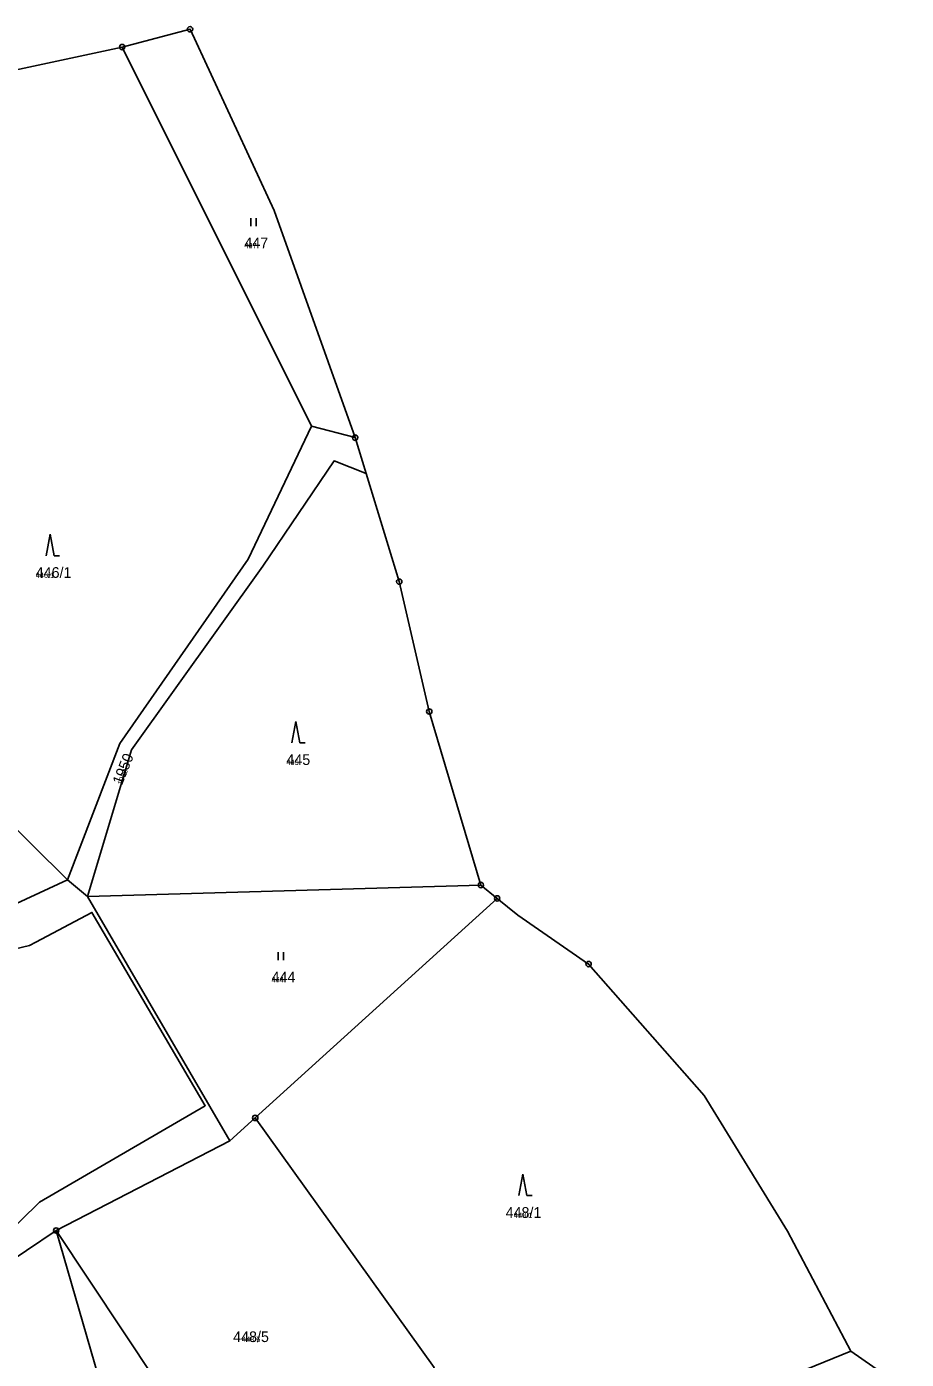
# Model space of a CAD drawing. Extents: x -763628 to -761565, y -976033 to -973833.
# Drawn here: x -761990.9 to -761826.2, y -974104.4 to -973855 of the extents above; entities that cross this region are included whole.
import ezdxf

# ---------------------------------------------------------------- set-up
doc = ezdxf.new("R2010")
doc.units = 0
for name, color, linetype in [('KN_cisla parcel 1000', 7, 'Continuous'), ('KN_cisla parcel 500', 7, 'Continuous'), ('KN_hranice parcel', 7, 'Continuous'), ('KN_hranice uzemi', 7, 'Continuous'), ('KN_znacky bodu BP', 7, 'Continuous'), ('KN_znacky kultur', 7, 'Continuous')]:
    doc.layers.add(name, color=color, linetype=linetype)

msp = doc.modelspace()

# ---------------------------------------------------------------- linework, layer by layer
at = {"layer": 'KN_hranice parcel'}
for p, q in [((-761937.58, -973929.76), (-761973.02, -973858.79)), ((-761937.58, -973929.76), (-761929.38, -973931.9)), ((-762035.47, -973963.03), (-761983.28, -974014.67)), ((-761983.28, -974014.67), (-761979.5, -974017.78)), ((-761905.85, -974015.63), (-761979.5, -974017.78)), ((-761979.5, -974017.78), (-761952.85, -974063.53)), ((-761948.1, -974059.22), (-761902.78, -974018.14)), ((-761952.85, -974063.53), (-761948.1, -974059.22)), ((-761952.85, -974063.53), (-761985.38, -974080.3)), ((-761985.38, -974080.3), (-762024.43, -974106.58)), ((-761976.43, -974111.24), (-761985.38, -974080.3))]:
    msp.add_line(p, q, dxfattribs=at)
for points in [[(-761983.28, -974014.67), (-761973.48, -973989.16), (-761949.45, -973954.64), (-761937.58, -973929.76)], [(-761927.32, -973938.61), (-761933.33, -973936.24), (-761946.68, -973955.95), (-761971.27, -973990.36), (-761979.5, -974017.78)], [(-762034.27, -973972.28), (-762024.59, -973979.11), (-762012.31, -974008.48), (-761996.38, -974020.73), (-761983.28, -974014.67)], [(-761994.56, -974027.98), (-761990.4, -974026.94), (-761989.2, -974026.35), (-761978.68, -974020.75), (-761957.46, -974056.95), (-761988.52, -974075.02), (-762005.87, -974091.94), (-762050.61, -974110.48), (-762074.41, -974109.33)], [(-761948.1, -974059.22), (-761914.58, -974105.93), (-761947.93, -974136.66), (-761985.38, -974080.3)], [(-761836.56, -974102.9), (-761855.09, -974110.42), (-761894.27, -974126.31)]]:
    msp.add_lwpolyline(points, dxfattribs=at)
at = {"layer": 'KN_hranice uzemi'}
for p, q in [((-761973.02, -973858.79), (-761960.31, -973855.47)), ((-761993.14, -973863.12), (-761973.02, -973858.79)), ((-761929.38, -973931.9), (-761927.32, -973938.61)), ((-761915.5, -973983.16), (-761905.85, -974015.63)), ((-761905.85, -974015.63), (-761902.78, -974018.14)), ((-761836.56, -974102.9), (-761826.15, -974110.09))]:
    msp.add_line(p, q, dxfattribs=at)
for points in [[(-761960.31, -973855.47), (-761944.58, -973889.38), (-761929.38, -973931.9)], [(-761927.32, -973938.61), (-761921.12, -973958.85), (-761915.5, -973983.16)], [(-761902.78, -974018.14), (-761898.91, -974021.3), (-761885.67, -974030.43)], [(-761885.67, -974030.43), (-761863.99, -974055.01), (-761848.4, -974080.42), (-761836.56, -974102.9)]]:
    msp.add_lwpolyline(points, dxfattribs=at)
at = {"layer": 'KN_znacky bodu BP'}
for centre, radius in [((-761960.31, -973855.47), 0.5), ((-761960.31, -973855.47), 0.0303), ((-761973.02, -973858.79), 0.5), ((-761973.02, -973858.79), 0.0303), ((-761929.38, -973931.9), 0.5), ((-761929.38, -973931.9), 0.0303), ((-761921.12, -973958.85), 0.5), ((-761921.12, -973958.85), 0.0303), ((-761915.5, -973983.16), 0.5), ((-761915.5, -973983.16), 0.0303), ((-761905.85, -974015.63), 0.5), ((-761905.85, -974015.63), 0.0303), ((-761902.78, -974018.14), 0.5), ((-761902.78, -974018.14), 0.0303), ((-761885.67, -974030.43), 0.5), ((-761885.67, -974030.43), 0.0303), ((-761948.1, -974059.22), 0.5), ((-761948.1, -974059.22), 0.0303), ((-761985.38, -974080.3), 0.5), ((-761985.38, -974080.3), 0.0303)]:
    msp.add_circle(centre, radius, dxfattribs=at)
at = {"layer": 'KN_znacky kultur'}
for p, q in [((-761948.95, -973892.3), (-761948.95, -973890.8)), ((-761947.95, -973892.3), (-761947.95, -973890.8)), ((-761986.49, -973949.99), (-761987.24, -973953.99)), ((-761985.74, -973953.99), (-761986.49, -973949.99)), ((-761985.74, -973953.99), (-761984.74, -973953.99)), ((-761940.49, -973985.02), (-761941.24, -973989.02)), ((-761939.74, -973989.02), (-761940.49, -973985.02)), ((-761939.74, -973989.02), (-761938.74, -973989.02)), ((-761943.83, -974029.72), (-761943.83, -974028.22)), ((-761942.83, -974029.72), (-761942.83, -974028.22)), ((-761898, -974069.73), (-761898.75, -974073.73)), ((-761897.25, -974073.73), (-761898, -974069.73)), ((-761897.25, -974073.73), (-761896.25, -974073.73))]:
    msp.add_line(p, q, dxfattribs=at)

# ---------------------------------------------------------------- texts
at = {"layer": 'KN_cisla parcel 1000'}
for s, p in [('447', (-761950.13, -973896.45)), ('446/1', (-761989.21, -973958.14)), ('445', (-761942.26, -973993.17)), ('444', (-761945.04, -974033.87)), ('448/1', (-761901.2, -974077.93)), ('448/5', (-761952.23, -974101.18))]:
    msp.add_text(s, height=2, dxfattribs=at).set_placement(p)
msp.add_text('1950', height=2, rotation=68, dxfattribs=at).set_placement((-761973.05, -973997.03))
at = {"layer": 'KN_cisla parcel 500'}
for s, p in [('447', (-761950.13, -973896.45)), ('446/1', (-761989.21, -973958.14)), ('445', (-761942.26, -973993.17)), ('444', (-761945.04, -974033.87)), ('448/1', (-761899.65, -974077.93)), ('448/5', (-761950.58, -974101.18))]:
    msp.add_text(s, height=1, dxfattribs=at).set_placement(p)
msp.add_text('1950', height=1, rotation=68, dxfattribs=at).set_placement((-761973.05, -973997.03))

doc.saveas('drawing.dxf')
